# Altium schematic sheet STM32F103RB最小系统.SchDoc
size A4
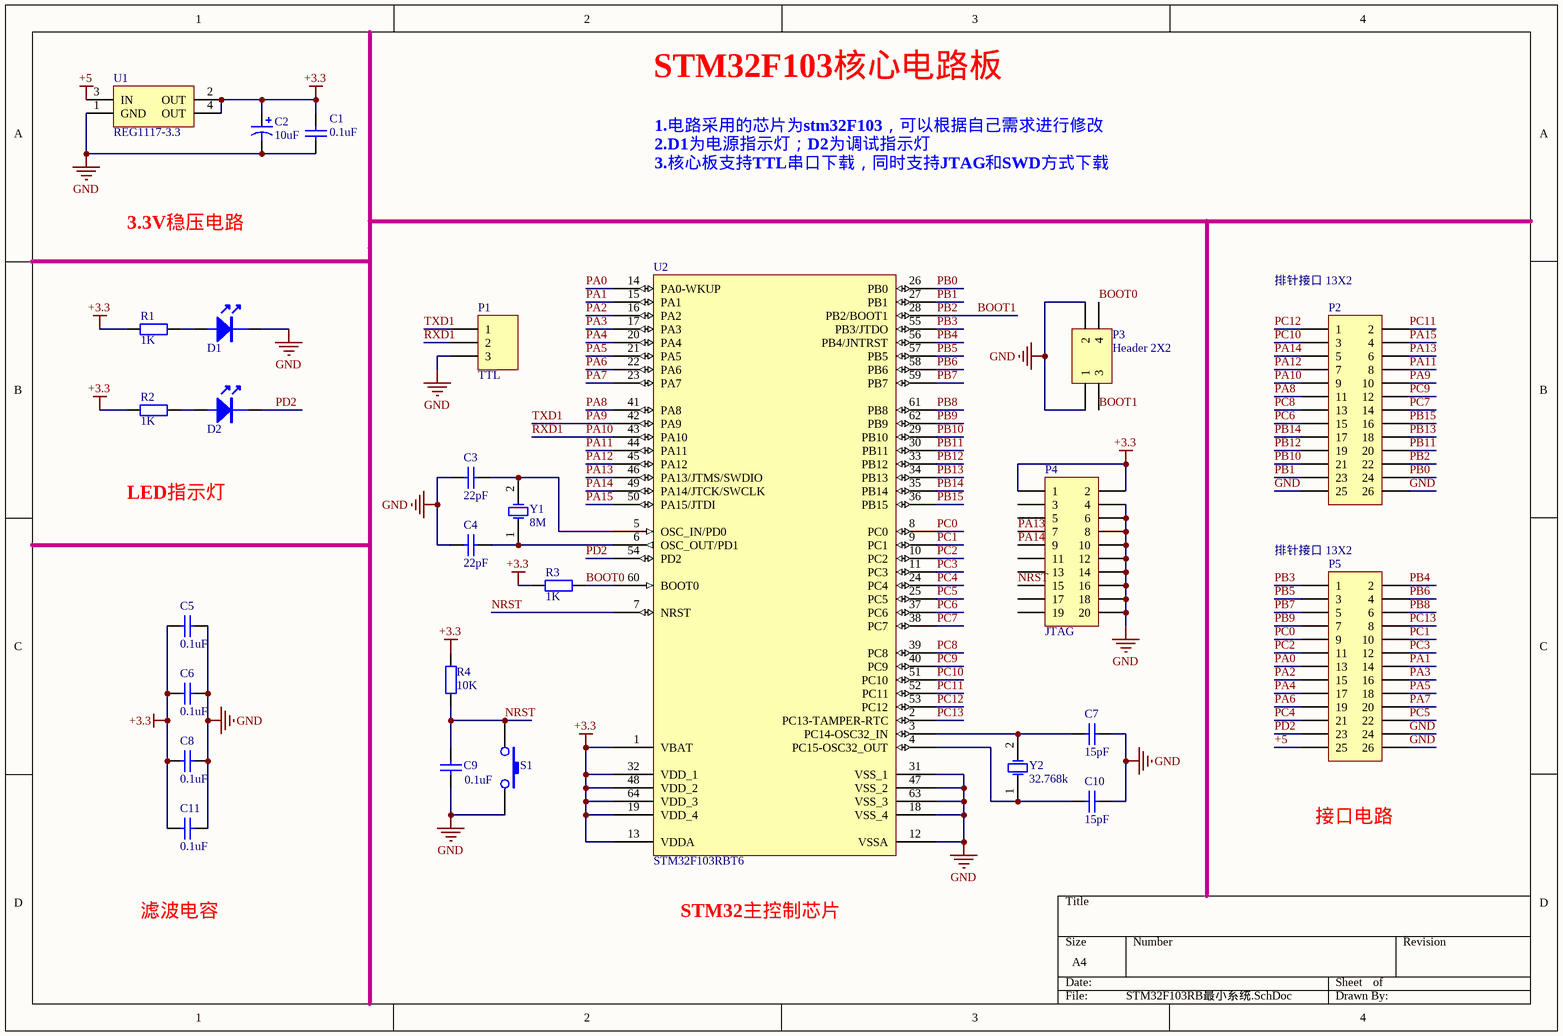
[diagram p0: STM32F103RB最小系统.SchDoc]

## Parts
C1  0.1uF  [0805C]
C2  10uF  [0805C]
C3  22pF  [0805C]
C4  22pF  [0805C]
C5  0.1uF  [0805C]
C6  0.1uF  [0805C]
C7  15pF  [0805C]
C8  0.1uF  [0805C]
C9  0.1uF  [0805C]
C10  15pF  [0805C]
C11  0.1uF  [0805C]
D1  LED  [LED0805]  (value not drawn)
D2  LED  [LED0805]  (value not drawn)
P1  TTL  [HDR1X3]
P2  排针接口 13X2  [HDR2X13]
P3  Header 2X2  [HDR2X2]
P4  JTAG  [JTAG20]
P5  排针接口 13X2  [HDR2X13]
R1  1K  [0805R]
R2  1K  [0805R]
R3  1K  [0805R]
R4  10K  [0805R]
S1  KEY  [KEY_SOP]  (value not drawn)
U1  REG1117-3.3  [ZZ311]
U2  STM32F103RBT6  [LQFP64_N]
Y1  8M  [OSC2PR-1]
Y2  32.768k  [XTAL-B]

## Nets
+3.3: C1.2 C2.1 C5.1 C6.1 C8.1 C11.1 P4.1 P4.2 R1.1 R2.1 R3.1 R4.2 U1.2(OUT) U1.4(OUT) U2.1(VBAT) U2.13(VDDA) U2.19(VDD_4) U2.32(VDD_1) U2.48(VDD_2) U2.64(VDD_3)
+5: P5.25 U1.3(IN)
GND: C1.1 C2.2 C3.1 C4.1 C5.2 C6.2 C7.2 C8.2 C9.1 C10.2 C11.2 D1.2 P1.3 P2.25 P2.26 P3.1 P3.2 P4.4 P4.6 P4.8 P4.10 P4.12 P4.14 P4.16 P4.18 P4.20 P5.24 P5.26 S1.2 U1.1(GND) U2.12(VSSA) U2.18(VSS_4) U2.31(VSS_1) U2.47(VSS_2) U2.63(VSS_3)
BOOT0: P3.4 R3.2 U2.60(BOOT0)
BOOT1: P2.22 P3.3 U2.28(PB2/BOOT1)  [also labelled PB2]
NRST: C9.2 P4.15 R4.1 S1.1 U2.7(NRST)
PA0: P5.13 U2.14(PA0-WKUP)
PA1: P5.14 U2.15(PA1)
PA2: P5.15 U2.16(PA2)
PA3: P5.16 U2.17(PA3)
PA4: P5.17 U2.20(PA4)
PA5: P5.18 U2.21(PA5)
PA6: P5.19 U2.22(PA6)
PA7: P5.20 U2.23(PA7)
PA8: P2.11 U2.41(PA8)
PA9: P1.1 P2.10 U2.42(PA9)  [also labelled TXD1]
PA10: P1.2 P2.9 U2.43(PA10)  [also labelled RXD1]
PA11: P2.8 U2.44(PA11)
PA12: P2.7 U2.45(PA12)
PA13: P2.6 P4.7 U2.46(PA13/JTMS/SWDIO)
PA14: P2.5 P4.9 U2.49(PA14/JTCK/SWCLK)
PA15: P2.4 U2.50(PA15/JTDI)
PB0: P2.24 U2.26(PB0)
PB1: P2.23 U2.27(PB1)
PB3: P5.1 U2.55(PB3/JTDO)
PB4: P5.2 U2.56(PB4/JNTRST)
PB5: P5.3 U2.57(PB5)
PB6: P5.4 U2.58(PB6)
PB7: P5.5 U2.59(PB7)
PB8: P5.6 U2.61(PB8)
PB9: P5.7 U2.62(PB9)
PB10: P2.21 U2.29(PB10)
PB11: P2.20 U2.30(PB11)
PB12: P2.19 U2.33(PB12)
PB13: P2.18 U2.34(PB13)
PB14: P2.17 U2.35(PB14)
PB15: P2.16 U2.36(PB15)
PC0: P5.9 U2.8(PC0)
PC1: P5.10 U2.9(PC1)
PC2: P5.11 U2.10(PC2)
PC3: P5.12 U2.11(PC3)
PC4: P5.21 U2.24(PC4)
PC5: P5.22 U2.25(PC5)
PC6: P2.15 U2.37(PC6)
PC7: P2.14 U2.38(PC7)
PC8: P2.13 U2.39(PC8)
PC9: P2.12 U2.40(PC9)
PC10: P2.3 U2.51(PC10)
PC11: P2.2 U2.52(PC11)
PC12: P2.1 U2.53(PC12)
PC13: P5.8 U2.2(PC13-TAMPER-RTC)
PD2: D2.2 P5.23 U2.54(PD2)
NetC3_2: C3.2 U2.5(OSC_IN/PD0) Y1.2(OSC2)
NetC4_2: C4.2 U2.6(OSC_OUT/PD1) Y1.1(OSC1)
NetC7_1: C7.1 U2.3(PC14-OSC32_IN) Y2.2(OSC2)
NetC10_1: C10.1 U2.4(PC15-OSC32_OUT) Y2.1(OSC1)
NetD1_1: D1.1 R1.2
NetD2_1: D2.1 R2.2

Not connected (* = marked no-connect by the designer): P4 3 5 11 13 17 19

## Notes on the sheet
- STM32F103核心电路板
- 3.3V稳压电路
- 1.电路采用的芯片为stm32F103，可以根据自己需求进行修改
  2.D1为电源指示灯；D2为调试指示灯
  3.核心板支持TTL串口下载，同时支持JTAG和SWD方式下载
- LED指示灯
- 接口电路
- 滤波电容
- STM32主控制芯片

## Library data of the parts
C1 C3-C11 = Cap: Capacitor
C2 = Cap Pol1: Polarized Capacitor (Radial)
P1 = Header 3: Header, 3-Pin
P2 P5 = Header 13X2: Header, 13-Pin, Dual row
P3 = Header 2X2: Header, 2-Pin, Dual row
P4 = Header 10X2: Header, 10-Pin, Dual row
R1-R4 = Res2: Resistor
U1 = REG1117-3.3: 800mA and 1A Low Dropout Positive Regulator 2.85V, 3.3V, 5V, and Adjustable
U2 = STM32F103RBT6: STM32 ARM-based 32-bit MCU with 128 Kbytes Flash, 64-pin LQFP, Industrial Temperature
Y1 Y2 = XTAL: Crystal Oscillator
